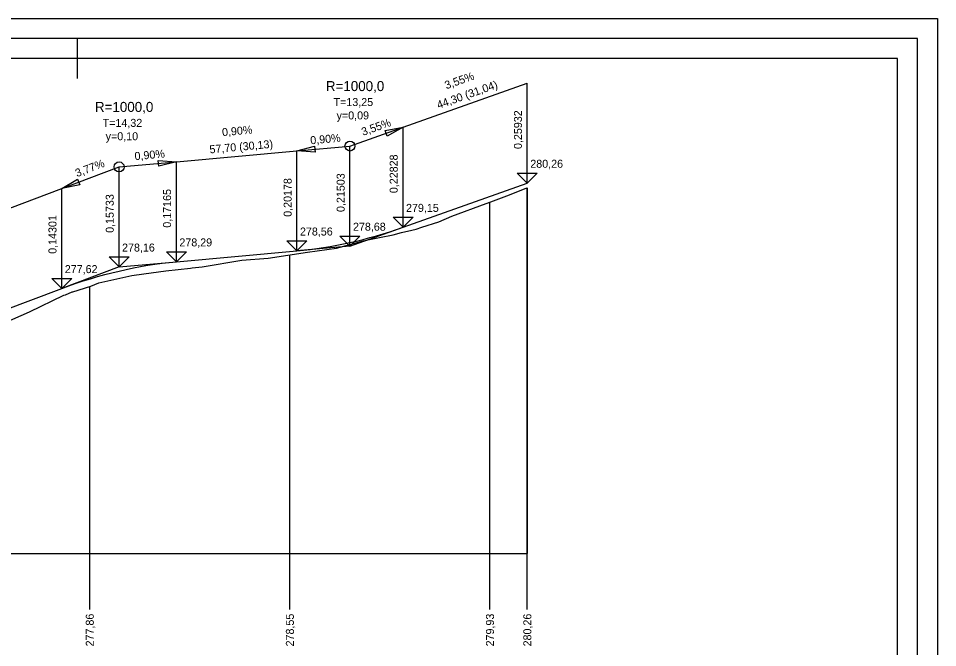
# Model space of a CAD drawing. Extents: x -761995 to -761565, y -1048251 to -1047944.
# Drawn here: x -761794.2 to -761564.5, y -1048101.4 to -1047944.1 of the extents above; entities that cross this region are included whole.
import ezdxf

# ---------------------------------------------------------------- set-up
doc = ezdxf.new("R2010")
doc.units = 0
for name, color, linetype in [('C3D-PROFIL-NIVELETA', 7, 'Continuous'), ('C3D-PROFIL-POPIS', 7, 'Continuous'), ('C3D-PROFIL-POPIS-NIVELETA', 7, 'Continuous'), ('C3D-PROFIL-TEREN', 7, 'Continuous'), ('C3D-ZOBPROF-PROUZEK-TEREN', 7, 'Continuous'), ('C3D-ZOBPROF-RASTR-VERHL', 7, 'Continuous'), ('C3D-ZOBPROF-RASTR-VERVEDL', 7, 'Continuous'), ('C3D-ZOBPROF-SROV-ROVINA', 7, 'Continuous'), ('Default', 7, 'Continuous'), ('U_formát', 7, 'Continuous'), ('U_rozvržení_rámeček', 7, 'Continuous')]:
    doc.layers.add(name, color=color, linetype=linetype)

# ---------------------------------------------------------------- blocks, each defined once
blk = doc.blocks.new('PP-sipka')
at = {"layer": 'Default'}
for p, q in [((0, 0), (-4, 4)), ((-4, 4), (4, 4)), ((4, 4), (0, 0))]:
    blk.add_line(p, q, dxfattribs=at)
blk = doc.blocks.new('AeccTickCircle')
at = {"layer": 'Default'}
blk.add_circle((0, 0), 0.5, dxfattribs=at)
blk = doc.blocks.new('AeccArwClosedFilled')
at = {"layer": 'Default'}
blk.add_lwpolyline([(0.18, 0.03), (0.18, -0.03), (0, 0)], close=True, dxfattribs=at)
blk = doc.blocks.new('U1096')
at = {"layer": 'Default'}
blk.add_line((-210, 0), (-210, -10), dxfattribs=at)
blk.add_lwpolyline([(0, -297), (0, 0), (-420, 0), (-420, -297)], close=True, dxfattribs=at)
at = {"layer": 'U_formát'}
for points in [[(-425, 5), (5, 5), (5, -302), (-425, -302)], [(-5, -292), (-5, -5), (-415, -5), (-415, -292)]]:
    blk.add_lwpolyline(points, close=True, dxfattribs=at)

msp = doc.modelspace()

# ---------------------------------------------------------------- linework, layer by layer
at = {"layer": 'C3D-PROFIL-NIVELETA'}
msp.add_lwpolyline([(-761926.36, -1048065.48), (-761783.34, -1048011.62), (-761781.55, -1048010.96), (-761779.76, -1048010.34), (-761777.98, -1048009.74), (-761776.19, -1048009.18), (-761774.4, -1048008.65), (-761772.61, -1048008.16), (-761770.82, -1048007.69), (-761769.03, -1048007.26), (-761767.24, -1048006.85), (-761765.45, -1048006.48), (-761763.66, -1048006.15), (-761761.87, -1048005.84), (-761760.08, -1048005.57), (-761758.29, -1048005.33), (-761756.5, -1048005.12), (-761754.71, -1048004.94), (-761724.58, -1048002.22), (-761722.92, -1048002.06), (-761721.27, -1048001.87), (-761719.61, -1048001.65), (-761717.95, -1048001.4), (-761716.3, -1048001.13), (-761714.64, -1048000.83), (-761712.98, -1048000.5), (-761711.33, -1048000.15), (-761709.67, -1047999.76), (-761708.02, -1047999.35), (-761706.36, -1047998.91), (-761704.7, -1047998.45), (-761703.05, -1047997.96), (-761701.39, -1047997.44), (-761699.73, -1047996.89), (-761698.08, -1047996.32), (-761667.03, -1047985.29)], dxfattribs=at)
at = {"layer": 'C3D-PROFIL-POPIS'}
msp.add_line((-761667.03, -1047986.59), (-761667.03, -1048077.86), dxfattribs=at)
at = {"layer": 'C3D-PROFIL-POPIS-NIVELETA'}
for p, q in [((-761698.08, -1047971.32), (-761667.03, -1047960.29)), ((-761667.03, -1047985.29), (-761667.03, -1047960.29)), ((-761711.33, -1047976.02), (-761698.08, -1047971.32)), ((-761698.08, -1047996.32), (-761698.08, -1047971.32)), ((-761698.08, -1047996.32), (-761698.08, -1047971.32)), ((-761724.58, -1047977.22), (-761711.33, -1047976.02)), ((-761711.33, -1048001.02), (-761711.33, -1047976.02)), ((-761754.71, -1047979.94), (-761724.58, -1047977.22)), ((-761724.58, -1048002.22), (-761724.58, -1047977.22)), ((-761724.58, -1048002.22), (-761724.58, -1047977.22)), ((-761769.03, -1047981.23), (-761754.71, -1047979.94)), ((-761754.71, -1048004.94), (-761754.71, -1047979.94)), ((-761754.71, -1048004.94), (-761754.71, -1047979.94)), ((-761783.34, -1047986.62), (-761769.03, -1047981.23)), ((-761769.03, -1048006.23), (-761769.03, -1047981.23)), ((-761926.36, -1048040.48), (-761783.34, -1047986.62)), ((-761783.34, -1048011.62), (-761783.34, -1047986.62)), ((-761783.34, -1048011.62), (-761783.34, -1047986.62)), ((-761711.33, -1048001.02), (-761698.08, -1047996.32)), ((-761711.33, -1048001.02), (-761724.58, -1048002.22)), ((-761769.03, -1048006.23), (-761783.34, -1048011.62)), ((-761769.03, -1048006.23), (-761754.71, -1048004.94))]:
    msp.add_line(p, q, dxfattribs=at)
at = {"layer": 'C3D-PROFIL-TEREN'}
msp.add_lwpolyline([(-761797.68, -1048020.19), (-761791.41, -1048017.48), (-761782.82, -1048013.34), (-761782.44, -1048013.19), (-761780.72, -1048012.49), (-761780.59, -1048012.45), (-761776.09, -1048011.09), (-761774.12, -1048010.25), (-761765.83, -1048008.38), (-761762.88, -1048007.98), (-761757.37, -1048007.24), (-761751.15, -1048006.52), (-761750.79, -1048006.48), (-761748.26, -1048006.19), (-761738.37, -1048004.55), (-761731.8, -1048004.07), (-761721.98, -1048002.54), (-761714.71, -1048001.53), (-761708.08, -1047999.69), (-761706.05, -1047999.27), (-761703.51, -1047998.77), (-761700.97, -1047998.3), (-761700.58, -1047998.23), (-761698.44, -1047997.66), (-761695.9, -1047997.03), (-761694.83, -1047996.77), (-761693.37, -1047996.31), (-761689.13, -1047994.98), (-761685.88, -1047993.56), (-761677.3, -1047990.36), (-761676.15, -1047990), (-761671.49, -1047988.21), (-761667.13, -1047986.45), (-761667.03, -1047986.59)], dxfattribs=at)
at = {"layer": 'C3D-ZOBPROF-PROUZEK-TEREN'}
for p, q in [((-761776.36, -1048082.86), (-761776.36, -1048077.86)), ((-761726.36, -1048082.86), (-761726.36, -1048077.86)), ((-761676.36, -1048082.86), (-761676.36, -1048077.86)), ((-761667.03, -1048082.86), (-761667.03, -1048077.86)), ((-761776.36, -1048091.86), (-761776.36, -1048082.86)), ((-761726.36, -1048091.86), (-761726.36, -1048082.86)), ((-761676.36, -1048091.86), (-761676.36, -1048082.86)), ((-761667.03, -1048091.86), (-761667.03, -1048082.86))]:
    msp.add_line(p, q, dxfattribs=at)
at = {"layer": 'C3D-ZOBPROF-RASTR-VERHL'}
for p, q in [((-761667.03, -1048077.86), (-761667.03, -1047986.59)), ((-761726.36, -1048077.86), (-761726.36, -1048003.22))]:
    msp.add_line(p, q, dxfattribs=at)
at = {"layer": 'C3D-ZOBPROF-RASTR-VERVEDL'}
for p, q in [((-761676.36, -1048077.86), (-761676.36, -1047990.06)), ((-761776.36, -1048077.86), (-761776.36, -1048011.18))]:
    msp.add_line(p, q, dxfattribs=at)
at = {"layer": 'C3D-ZOBPROF-SROV-ROVINA'}
msp.add_line((-761926.36, -1048077.86), (-761667.03, -1048077.86), dxfattribs=at)

# ---------------------------------------------------------------- block references
at = {"layer": 'C3D-PROFIL-POPIS-NIVELETA'}
for name, p, xscale, yscale, rotation in [('AeccArwClosedFilled', (-761698.08, -1047971.32), 24.99999999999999, 24.999999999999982, -160.44082579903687), ('AeccArwClosedFilled', (-761724.58, -1047977.22), 24.99999999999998, 24.999999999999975, 5.157691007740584), ('AeccTickCircle', (-761711.33, -1047976.02), 2.5000000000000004, 2.5000000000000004, 90.00000000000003), ('AeccTickCircle', (-761769.03, -1047981.23), 2.5000000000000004, 2.5000000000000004, 90.00000000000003), ('AeccArwClosedFilled', (-761754.71, -1047979.94), 24.999999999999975, 24.999999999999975, -174.842308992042), ('AeccArwClosedFilled', (-761783.34, -1047986.62), 24.99999999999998, 24.999999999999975, 20.63590349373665)]:
    msp.add_blockref(name, p, dxfattribs=dict(at, xscale=xscale, yscale=yscale, rotation=rotation))
at = {"layer": 'C3D-PROFIL-POPIS-NIVELETA', "xscale": 0.625, "yscale": 0.625}
for p in [(-761667.03, -1047985.29), (-761667.03, -1047985.29), (-761698.08, -1047996.32), (-761711.33, -1048001.02), (-761724.58, -1048002.22), (-761769.03, -1048006.23), (-761754.71, -1048004.94), (-761783.34, -1048011.62)]:
    msp.add_blockref('PP-sipka', p, dxfattribs=at)
at = {"layer": 'U_rozvržení_rámeček'}
msp.add_blockref('U1096', (-761569.51, -1047949.1), dxfattribs=at)

# ---------------------------------------------------------------- texts
at = {"layer": 'C3D-PROFIL-POPIS-NIVELETA'}
for s, rotation, p in [('3,55%', 19.5592, (-761687.25, -1047961.84)), ('44,30 (31,04)', 19.5592, (-761689.22, -1047966.78)), ('3,55%', 19.5592, (-761708.06, -1047973.48)), ('0,25932', 90, (-761668.36, -1047976.76)), ('0,25932', 90, (-761668.36, -1047976.76)), ('0,90%', 5.1577, (-761743.21, -1047973.57)), ('0,90%', 5.1577, (-761721.16, -1047975.6)), ('57,70 (30,13)', 5.1577, (-761746.34, -1047977.87)), ('0,90%', 5.1577, (-761765.07, -1047979.56)), ('0,22828', 90, (-761699.41, -1047987.8)), ('3,77%', 20.6359, (-761779.55, -1047983.8)), ('0,21503', 90, (-761712.66, -1047992.51)), ('0,20178', 90, (-761725.91, -1047993.71)), ('0,17165', 90, (-761756.04, -1047996.43)), ('0,15733', 90, (-761770.36, -1047997.72)), ('0,14301', 90, (-761784.67, -1048002.96))]:
    msp.add_text(s, height=2, rotation=rotation, dxfattribs=at).set_placement(p)
for s, height, p in [('R=1000,0', 2.5, (-761717.36, -1047962.28)), ('T=13,25', 2, (-761715.44, -1047966.02)), ('R=1000,0', 2.5, (-761775.06, -1047967.49)), ('T=14,32', 2, (-761773.13, -1047971.23)), ('y=0,09', 2, (-761714.68, -1047969.36)), ('y=0,10', 2, (-761772.38, -1047974.57)), ('280,26', 2, (-761666.28, -1047981.45)), ('280,26', 2, (-761666.28, -1047981.45)), ('279,15', 2, (-761697.33, -1047992.48)), ('278,56', 2, (-761723.83, -1047998.39)), ('278,68', 2, (-761710.58, -1047997.19)), ('278,29', 2, (-761753.96, -1048001.11)), ('278,16', 2, (-761768.28, -1048002.4)), ('277,62', 2, (-761782.59, -1048007.79))]:
    msp.add_text(s, height=height, dxfattribs=at).set_placement(p)
at = {"layer": 'C3D-ZOBPROF-PROUZEK-TEREN'}
for s, p in [('277,86', (-761775.35, -1048101.11)), ('278,55', (-761725.35, -1048101.11)), ('279,93', (-761675.35, -1048101.11)), ('280,26', (-761666.02, -1048101.11))]:
    msp.add_text(s, height=2, rotation=90, dxfattribs=at).set_placement(p)

doc.saveas('drawing.dxf')
